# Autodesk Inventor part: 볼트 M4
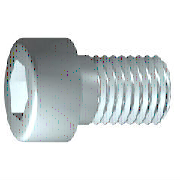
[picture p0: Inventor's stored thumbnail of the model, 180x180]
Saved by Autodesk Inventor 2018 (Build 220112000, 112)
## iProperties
IsCustomPart: 1
Created: 2012-02
Part Number: 볼트 M4
Material: 강철, 연강
Description: 6각머리 태핑 나사
Document SubType Name: Modeling
Standard: KS B 1003
Designer: mduedu
Standards Organization: KS
Language: ko-KR
Size Designation: M 4 x 10
Categories: <MemberInstance><Categories><Category DisplayName="조임쇠" InternalName="e4da775c-781d-43d5-af7c-5136215cf5a6" Mnemonic="FSTN"><Category DisplayName="볼트" InternalN
Density: 1 g/cm^3
Appearance: 강철
Author: mduedu
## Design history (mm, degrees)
sketch "스케치1"
  geometry: L1 (-1, 0)-(10, 0); L2 (10, 0)-(10, 2); L3 (10, 2)-(1.75, 2); L4 (1.75, 2)-(1.32, 2); L5 (1.32, 2)-(0, 2); L6 (0, 2)-(0, 3.5); L7 (0, 3.5)-(-4, 3.5); L8 (-4, 3.5)-(-4, 1.732); L9 (-4, 1.732)-(-2, 1.732); L10 (-2, 1.732)-(-1, 0); L11 (-6.8, 0)-(12.8, 0) reference; L12 (0, -0.7)-(0, 4.2) reference; L13 (1.75, 2)-(0, 2)
  constraints: 22 end point, 6 parallel, 2 collinear, 2 perpendicular, 1 horizontal, 1 point on line
  dimensions: "d1" = 8.25 distance from line of L3.end L2 (= GEL); "d2" = 0.42952 distance of L4.end L3.end (computed from GAL); "d3" = 4 distance between parallel lines of L8 L6 (= KOH); "d4" = 2 distance of L8.end L9.end (= INTI); "d5" = 60 deg angle of L10 L1; "d6" = 4 diameter of L3 L1 (= GD); "d7" = 4 diameter of L5 L1 (= BDM); "d8" = 3.4641 diameter of L9 L1 (= 1.1547 x SW); "d9" = 7 diameter of L7 L1 (= KOD); "d26" = 10 distance between parallel lines of L12 L2 (= NLG)
revolve "본체" sketch "스케치1" stored, may be unused: angle "d10" = 90 deg
sketch "스케치2"
  geometry: L1 (0, -4.9)-(0, 4.9) reference; L2 (-4.9, 0)-(4.9, 0) reference; L3 (1.732, 0)-(0.866, -1.5); L4 (0.866, -1.5)-(-0.866, -1.5); L5 (-0.866, -1.5)-(-1.732, 0); L6 (-1.732, 0)-(-0.866, 1.5); L7 (-0.866, 1.5)-(0.866, 1.5); L8 (0.866, 1.5)-(1.732, 0); 2 further points
  constraints: 12 end point, 1 coincident, 1 horizontal alignment, 1 point on line, 12 other
extrude "슬롯" join sketch "스케치2" stored distance "d11" = 10; taper "d12" = 0 deg
workplane "Work Plane1"
fillet "Fillet2" dims "d30" = 0.1 (= R)
body "Solid1"
fillet "모깎기1" dims "d17" = 0.4 (= RR)
feature "스레드" dims "d13" = 8.25 (= GEL), "d14" = 0
chamfer "모따기1" distance "d15" = 0.42941 (= -0.5 x SPD + 0.5 x GD); stored, may be unused: second distance "d16" = 0.42941 (= GUL), angle "d27" = 45 deg
other parameters: "GD" = 4 (= NND) [user parameter; used in 2 equation terms], "NLG" = 10 [user parameter; used in 1 equation term], "GEL" = 8.25 [user parameter; used in 2 equation terms], "KOD" = 7 [user parameter; used in 1 equation term], "KOH" = 4 [user parameter; used in 1 equation term], "INTI" = 2 [user parameter; used in 1 equation term], "GAL" = 0.42941 (= 0.61345 x PTC) [user parameter; used in 1 equation term], "GUL" = 0.42941 (= 0.61345 x PTC) [user parameter; used in 1 equation term], "BDM" = 4 (= NND) [user parameter; used in 1 equation term], "SW" = 3 [user parameter; used in 2 equation terms], "RR" = 0.4 [user parameter; used in 1 equation term], "SPD" = 3.14117 (= NND - 1.2269 x PTC) [user parameter; used in 1 equation term], "d19" = 0, "d28" = 0, "d29" = 0, "R" = 0.1 [user parameter; used in 1 equation term], "PHH" = 0.2 [user parameter], "GD1" = 3.14117 (= THREADDIA - 1.2269 x PTC) [user parameter], "THREADDIA" = 4 [user parameter; used in 1 equation term], "FAWI" = 45 deg [user parameter], "TPU" = 14.28571 (computed from PTC) [user parameter], "PTC" = 0.7 [user parameter; used in 5 equation terms], "NND" = 4 [user parameter; used in 3 equation terms], "TOA" = 30 deg [user parameter], "E0" = 3.465 (= 1.155 x SW) [user parameter]
